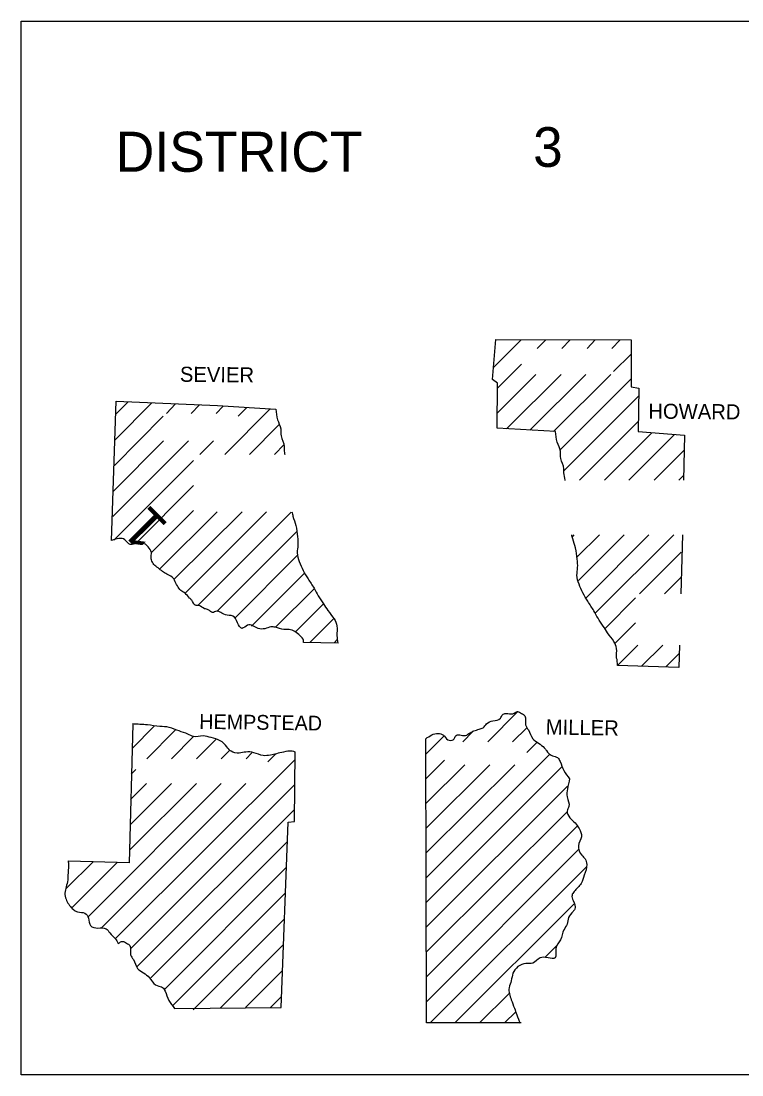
# Model space of a CAD drawing. Extents: x 76 to 6945, y -3933 to 2152.
# Drawn here: x 6298.9 to 6504, y -1915.6 to -1615.6 of the extents above; entities that cross this region are included whole.
import ezdxf

# ---------------------------------------------------------------- set-up
doc = ezdxf.new("R2010")
doc.units = 0
doc.layers.add('R_Draft', color=7, linetype='Continuous')

msp = doc.modelspace()

# ---------------------------------------------------------------- linework, layer by layer
at = {"layer": 'R_Draft'}
msp.add_line((6468.6, -1799.03), (6468.5, -1797.33), dxfattribs=at)
msp.add_lwpolyline([(6298.93, -1915.55), (6298.93, -1615.55), (6698.93, -1615.55), (6698.93, -1915.55)], close=True, dxfattribs=at)
for points in [[(6434.4, -1731.43), (6434.5, -1718.63), (6433.1, -1717.63), (6434, -1706.23), (6472.5, -1706.33)], [(6433.4, -1714.13), (6441.2, -1706.33)], [(6434, -1706.43), (6434.1, -1706.33)], [(6445.8, -1708.73), (6448.2, -1706.33)], [(6452.8, -1708.73), (6455.2, -1706.33)], [(6460, -1708.73), (6462.3, -1706.33)], [(6467, -1708.73), (6469.4, -1706.33)], [(6472.5, -1706.33), (6472.5, -1719.63), (6474.7, -1720.03), (6474.5, -1732.43), (6487.7, -1733.43), (6487.4, -1746.23)], [(6467.5, -1715.33), (6472.5, -1710.33)], [(6434.4, -1720.13), (6441.3, -1713.23)], [(6434.4, -1727.13), (6445.4, -1716.13)], [(6437.1, -1731.63), (6452.6, -1716.13)], [(6443.7, -1732.03), (6459.6, -1716.13)], [(6450.4, -1732.43), (6466.7, -1716.13)], [(6452.3, -1737.63), (6472.5, -1717.43)], [(6324.7, -1763.43), (6326, -1723.73)], [(6325.7, -1734.73), (6336.1, -1724.23)], [(6326, -1723.73), (6354.8, -1725.03)], [(6326, -1727.33), (6329.4, -1723.93)], [(6340.3, -1727.23), (6342.9, -1724.53)], [(6347.3, -1727.23), (6349.7, -1724.83)], [(6453.5, -1743.53), (6474.6, -1722.33)], [(6354.4, -1727.23), (6356.4, -1725.13)], [(6354.8, -1725.03), (6371.4, -1726.03)], [(6356.9, -1738.93), (6369.8, -1725.93)], [(6360.7, -1728.03), (6363.1, -1725.63)], [(6325.5, -1742.03), (6339.4, -1728.03)], [(6363.9, -1738.93), (6372.3, -1730.53)], [(6457.8, -1746.23), (6474.5, -1729.53)], [(6451, -1732.43), (6434.4, -1731.43)], [(6464.9, -1746.23), (6478.4, -1732.73)], [(6471.9, -1746.23), (6484.9, -1733.23)], [(6325, -1756.63), (6346.6, -1735.03)], [(6325.2, -1749.33), (6339.5, -1735.03)], [(6349.8, -1738.93), (6353.7, -1735.03)], [(6371, -1738.93), (6373.8, -1736.13)], [(6479.1, -1746.23), (6487.6, -1737.73)], [(6325.3, -1763.33), (6348, -1740.63)], [(6486.1, -1746.23), (6487.4, -1744.93)], [(6331.5, -1764.33), (6348, -1747.73)], [(6336, -1766.83), (6348, -1754.83)], [(6338.3, -1771.53), (6354.7, -1755.23)], [(6342.5, -1774.43), (6361.8, -1755.23)], [(6345.6, -1778.43), (6368.8, -1755.23)], [(6349.3, -1781.83), (6375.8, -1755.33)], [(6354.6, -1783.63), (6377.4, -1760.83)], [(6455.8, -1762.33), (6456.3, -1761.83)], [(6457.2, -1768.03), (6463.5, -1761.83)], [(6457.5, -1774.83), (6470.5, -1761.83)], [(6459.7, -1779.73), (6477.6, -1761.83)], [(6462.3, -1784.13), (6484.7, -1761.83)], [(6487.1, -1761.83), (6486.7, -1778.63)], [(6474.9, -1778.63), (6486.8, -1766.73)], [(6359.8, -1785.53), (6377.5, -1767.73)], [(6364.5, -1787.83), (6379.6, -1772.73)], [(6482, -1778.63), (6486.7, -1773.93)], [(6371.3, -1788.13), (6382.3, -1777.13)], [(6377, -1789.43), (6385, -1781.43)], [(6465.1, -1788.43), (6473.8, -1779.73)], [(6381.1, -1792.43), (6387.9, -1785.63)], [(6468, -1792.63), (6473.8, -1786.83)], [(6389.2, -1792.63), (6379.3, -1792.43)], [(6388, -1792.53), (6389, -1791.53)], [(6468.6, -1799.03), (6474.4, -1793.23)], [(6486.3, -1793.23), (6486.1, -1799.53), (6468.6, -1799.03)], [(6475.5, -1799.23), (6481.5, -1793.23)], [(6482.5, -1799.33), (6486.3, -1795.53)], [(6431.7, -1820.73), (6440.3, -1812.13)], [(6330.7, -1815.73), (6329.7, -1855.13), (6312.4, -1854.73)], [(6330.5, -1822.63), (6336.8, -1816.23)], [(6334.7, -1825.53), (6342.8, -1817.43)], [(6424.6, -1820.73), (6427.5, -1817.83)], [(6438.8, -1820.73), (6442.9, -1816.63)], [(6341.7, -1825.53), (6348, -1819.23)], [(6348.8, -1825.53), (6354.3, -1820.03)], [(6414.1, -1824.23), (6419.3, -1819.03)], [(6441.2, -1900.73), (6414.3, -1900.73), (6414.1, -1819.83)], [(6442.8, -1823.73), (6445.8, -1820.83)], [(6355.9, -1825.53), (6358.3, -1823.13)], [(6363, -1825.53), (6364.6, -1823.83)], [(6372.9, -1896.33), (6374.9, -1843.63), (6376.7, -1843.43), (6376.9, -1823.53)], [(6325.8, -1876.73), (6376.9, -1825.73)], [(6369.1, -1826.43), (6371.4, -1824.13)], [(6414.1, -1831.23), (6419.4, -1825.93)], [(6414.2, -1859.43), (6449.4, -1824.23)], [(6330.3, -1829.93), (6331.6, -1828.63)], [(6414.2, -1852.33), (6439.4, -1827.23)], [(6414.2, -1845.33), (6432.3, -1827.23)], [(6414.2, -1838.23), (6425.2, -1827.23)], [(6414.2, -1866.43), (6452.8, -1827.83)], [(6318, -1870.53), (6355.9, -1832.63)], [(6321.9, -1873.63), (6362.9, -1832.63)], [(6329.8, -1851.53), (6348.8, -1832.63)], [(6330, -1844.33), (6341.7, -1832.63)], [(6330.1, -1837.13), (6334.6, -1832.63)], [(6330.1, -1879.63), (6376.8, -1832.83)], [(6414.2, -1873.53), (6454.4, -1833.33)], [(6332, -1884.73), (6376.7, -1840.03)], [(6414.3, -1880.53), (6454.3, -1840.63)], [(6414.3, -1887.63), (6457.2, -1844.73)], [(6335.7, -1888.13), (6374.7, -1849.13)], [(6414.3, -1894.73), (6457.6, -1851.33)], [(6311.9, -1862.43), (6319.5, -1854.83)], [(6313.4, -1868.03), (6326.4, -1855.03)], [(6339.7, -1891.23), (6374.4, -1856.53)], [(6415.3, -1900.73), (6459.8, -1856.33)], [(6342, -1895.93), (6374.1, -1863.83)], [(6422.4, -1900.73), (6456.2, -1866.93)], [(6347.9, -1897.03), (6348.4, -1896.53), (6373.8, -1871.23)], [(6355.7, -1896.43), (6373.5, -1878.53)], [(6448, -1882.13), (6451.6, -1878.53)], [(6362.8, -1896.33), (6373.3, -1885.83)], [(6429.4, -1900.73), (6437.8, -1892.33)], [(6369.9, -1896.33), (6373, -1893.23)], [(6342.6, -1896.63), (6372.9, -1896.33)], [(6436.5, -1900.73), (6439.7, -1897.63)]]:
    msp.add_lwpolyline(points, dxfattribs=at)
for points in [[(6371.4, -1726.03), (6371.9, -1729.03), (6372.8, -1731.63), (6372.9, -1733.63), (6373.8, -1736.63), (6373.8, -1737.73), (6374, -1738.93)], [(6453.7, -1746.33), (6453.7, -1746.23), (6453.4, -1744.13), (6453.4, -1743.03), (6452.5, -1740.03), (6452.4, -1738.03), (6451.5, -1735.43), (6451, -1732.43)], [(6376, -1755.23), (6376.3, -1756.53), (6377.1, -1759.13), (6377.6, -1762.33), (6377.7, -1764.73), (6377.5, -1766.93), (6378.1, -1769.43), (6379.2, -1771.93), (6380.6, -1774.33), (6382.3, -1777.03), (6383.5, -1779.13), (6385, -1781.43), (6386.2, -1783.33), (6388, -1785.73), (6388.8, -1787.73), (6388.8, -1790.53), (6389.1, -1792.63)], [(6379.3, -1792.43), (6379.3, -1791.83), (6378.3, -1790.53), (6376.8, -1789.33), (6375.2, -1788.73), (6373.7, -1788.73), (6371.3, -1788.13), (6370, -1788.03), (6368.3, -1788.53), (6366.4, -1788.43), (6363.4, -1787.53), (6361.8, -1788.43), (6360.5, -1786.83), (6359.2, -1784.93), (6358.1, -1784.73), (6356.1, -1784.13), (6354.6, -1783.53), (6353.4, -1783.93), (6352.2, -1783.13), (6351.1, -1782.83), (6349.6, -1781.93), (6348.5, -1781.83), (6347.5, -1780.43), (6346.9, -1779.83), (6345.6, -1778.43), (6344.4, -1777.63), (6343.4, -1776.33), (6342.6, -1774.73), (6342.4, -1774.33), (6340.4, -1773.03), (6339.2, -1772.23), (6337.9, -1771.23), (6336.7, -1770.23), (6336, -1768.93), (6335.9, -1768.33), (6336, -1766.83), (6335.1, -1765.23), (6334, -1764.33), (6332.5, -1764.23), (6330.9, -1764.43), (6330, -1764.53), (6328.5, -1763.23), (6324.7, -1763.43)], [(6468.5, -1797.33), (6468.4, -1796.93), (6468.4, -1794.13), (6467.6, -1792.13), (6465.8, -1789.73), (6464.6, -1787.83), (6463.1, -1785.53), (6461.9, -1783.43), (6460.2, -1780.73), (6458.8, -1778.33), (6457.7, -1775.83), (6457.1, -1773.33), (6457.3, -1771.13), (6457.2, -1768.73), (6456.7, -1765.53), (6455.9, -1762.93), (6455.6, -1761.83)], [(6414.1, -1819.83), (6417.6, -1818.33), (6419.1, -1818.83), (6420.4, -1820.13), (6421.9, -1820.13), (6422.7, -1818.93), (6424.2, -1818.83), (6425.4, -1818.93), (6426.7, -1818.13), (6427.8, -1817.63), (6429.3, -1817.13), (6430.4, -1816.73), (6431.4, -1815.63), (6433.2, -1814.73), (6435.3, -1814.03), (6435.9, -1813.03), (6436.9, -1812.63), (6438.9, -1812.73), (6440.2, -1812.13), (6441.3, -1812.63), (6442.3, -1813.33), (6442.5, -1815.93), (6443.3, -1817.33), (6444.5, -1819.83), (6446.2, -1821.13), (6447.8, -1822.43), (6448.4, -1823.23), (6450.1, -1824.73), (6451.6, -1825.23), (6452.3, -1826.33), (6453.4, -1828.93), (6455, -1831.23)], [(6376.9, -1823.63), (6376.1, -1823.43), (6373.6, -1823.63), (6371.6, -1824.13), (6369.9, -1824.53), (6367.8, -1824.63), (6365.2, -1823.83), (6362.9, -1823.63), (6361, -1823.93), (6358.7, -1823.43), (6357.5, -1822.13), (6355.6, -1820.43), (6353, -1819.53), (6350.7, -1819.03), (6348, -1819.23), (6346.4, -1818.53), (6343.9, -1817.63), (6341.1, -1816.63), (6338.4, -1816.33), (6334.9, -1815.93), (6330.6, -1815.63)], [(6455, -1831.23), (6454.4, -1834.13), (6454.3, -1836.43), (6454.8, -1839.13), (6454.3, -1840.43), (6455.1, -1842.33), (6456.6, -1843.83), (6457.7, -1845.43), (6458.4, -1847.73), (6457.5, -1850.33), (6458.5, -1853.03), (6459.4, -1854.03), (6459.9, -1855.63), (6459.2, -1858.73), (6458.3, -1861.03), (6456.3, -1863.33), (6455.7, -1864.43), (6456, -1865.93), (6456.5, -1868.33), (6456, -1869.03), (6454.7, -1870.73), (6454.3, -1872.63), (6453.4, -1874.23), (6452.4, -1877.13), (6451.1, -1879.53), (6450.9, -1882.23), (6448.9, -1882.23), (6446.6, -1882.23), (6444.5, -1883.73), (6442.6, -1883.83), (6440.3, -1884.73), (6438.9, -1886.63), (6438.4, -1888.73), (6437.8, -1890.73), (6438.4, -1894.13), (6439.3, -1896.53), (6440, -1898.43), (6440.9, -1900.83)], [(6312.3, -1854.63), (6312.4, -1855.13), (6312.3, -1858.03), (6312.1, -1860.63), (6311.4, -1864.23), (6311.9, -1865.93), (6313.8, -1868.43), (6315, -1869.13), (6317.1, -1869.53), (6318.1, -1870.93), (6318.7, -1873.03), (6320.8, -1873.73), (6323.1, -1873.93), (6324.2, -1875.13), (6325.7, -1876.73), (6326.6, -1878.13)], [(6326.6, -1878.13), (6327.8, -1877.53), (6328.9, -1878.03), (6329.9, -1878.73), (6330.1, -1881.33), (6330.9, -1882.73), (6332.1, -1885.23), (6333.8, -1886.53), (6335.4, -1887.83), (6336, -1888.63), (6337.7, -1890.13), (6339.2, -1890.63), (6339.9, -1891.73), (6341, -1894.33), (6342.6, -1896.63)]]:
    msp.add_spline(points, degree=3, dxfattribs=at)

# ---------------------------------------------------------------- texts
for s, height, p in [('DISTRICT', 11.4, (6325.83, -1658.45)), ('3', 11.3, (6444.63, -1657.05))]:
    msp.add_text(s, height=height, dxfattribs=at).set_placement(p)
for s, height, rotation, p in [('SEVIER', 4.301, 359.4271, (6344.1, -1718.23)), ('HOWARD', 4.301, 359.5145, (6477.4, -1728.73)), ('1', 11.4, 135, (6341.2, -1759.03)), ('HEMPSTEAD', 4.199, 359.1885, (6349.6, -1817.03)), ('MILLER', 4.3, 359.1319, (6448.2, -1818.63))]:
    msp.add_text(s, height=height, rotation=rotation, dxfattribs=at).set_placement(p)

doc.saveas('drawing.dxf')
